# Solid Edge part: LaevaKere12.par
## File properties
Author: Egon 815
Template: Normal.par
Last saved by: egono
Revision: 95
Application: Solid Edge
Accuracy: 0,990
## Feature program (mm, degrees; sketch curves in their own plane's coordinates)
boolean "unnamed Boolean 1"
sketch for "unnamed Protrusion 1" #1 plane through (16818.4775, 0, 0) normal (1, 0, 0) x-axis (0, 1, 0)
  arc centre (22553.4282, -4878.3254) radius 21853.533 from (699.8952, -4878.3254) to (5128.0164, 8310) cw
  arc centre (-22553.4282, -4878.3254) radius 21853.533 from (-699.8952, -4878.3254) to (-5128.0164, 8310) ccw
  line (-5128.0164, 8310) -> (5128.0164, 8310)
  arc centre (0, -4878.3254) radius 699.8952 from (-699.8952, -4878.3254) to (0, -5578.2207) ccw
  arc centre (0, -4878.3254) radius 699.8952 from (0, -5578.2207) to (699.8952, -4878.3254) ccw
sketch for "unnamed Protrusion 1" #2 plane through (16818.4775, 0, 0) normal (1, 0, 0) x-axis (0, 1, 0)
sketch for "unnamed Protrusion 1" #3 plane through (16818.4775, 0, 0) normal (1, 0, 0) x-axis (0, 1, 0)
sketch for "unnamed Protrusion 1" #4 plane through (16818.4775, 0, 0) normal (1, 0, 0) x-axis (0, 1, 0)
sketch for "unnamed Protrusion 1" #5 plane through (16818.4775, 0, 0) normal (1, 0, 0) x-axis (0, 1, 0)
sketch for "unnamed Protrusion 1" #6 plane through (16818.4775, 0, 0) normal (1, 0, 0) x-axis (0, 1, 0)
sketch for "unnamed Protrusion 1" #7 plane through (16818.4775, 0, 0) normal (1, 0, 0) x-axis (0, 1, 0)
sketch for "unnamed Protrusion 1" #8 plane through (16818.4775, 0, 0) normal (1, 0, 0) x-axis (0, 1, 0)
sketch for "unnamed Protrusion 1" #9 plane through (16818.4775, 0, 0) normal (1, 0, 0) x-axis (0, 1, 0)
sketch for "unnamed Protrusion 1" #10 plane through (16818.4775, 0, 0) normal (1, 0, 0) x-axis (0, 1, 0)
sketch for "unnamed Protrusion 1" #11 plane through (16818.4775, 0, 0) normal (1, 0, 0) x-axis (0, 1, 0)
sketch for "unnamed Protrusion 1" #12 plane through (16818.4775, 0, 0) normal (1, 0, 0) x-axis (0, 1, 0)
sketch for "unnamed Protrusion 1" #13 plane through (16818.4775, 0, 0) normal (1, 0, 0) x-axis (0, 1, 0)
  line (-55694.7482, 3362.4841) -> (-45802.5294, 3362.4841)
  line (-45802.5294, 3362.4841) -> (-45802.5294, 843.2206)
  line (-45802.5294, 843.2206) -> (-55694.7482, 843.2206)
sketch for "unnamed Protrusion 1" #14 plane through (16818.4775, 0, 0) normal (1, 0, 0) x-axis (0, 1, 0)
extrude "unnamed Protrusion 1" add through along -normal
boolean "unnamed Boolean 2"
sketch used by "ExtrudedProtrusion_12" plane through (0, 0, 0) normal (1, 0, 0) x-axis (0, 1, 0)
extrude "ExtrudedProtrusion_12" add finite 37845.8186 along -normal
replace surface "unnamed ReplaceSurface 1"
replace surface "unnamed ReplaceSurface 2"
body pattern "unnamed BodyPattern 1"
pattern "unnamed Pattern 1"
lofted protrusion "LoftedProtrusion_35"  StartTangentMagnitude1 = 1; EndTangentMagnitude1 = 1
sketch used by "unnamed Cutout 1" plane through (0, 0, 0) normal (1, 0, 0) x-axis (0, 1, 0)
  line (-111469.4186, 8314.9532) -> (-66244.3403, 7184.8312)
  line (-44381.2454, 5032.5774) -> (-59033.8334, 5032.5774)
  line (-59033.8334, 5032.5774) -> (-66244.3403, 7184.8312)
  line (-44381.2454, 5032.5774) -> (120116.3176, 5032.5774)
extrude "unnamed Cutout 1" cut through
Other named dimensions: "ExtrudedSurface_10": FiniteDepth = 28411.8747 mm | "OffsetSurface_9": Distance = 60 mm
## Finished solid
Body 1: sheet body, 1 face, 4 edges, 4 vertices.
  Faces by surface: offset 1
  Edges by curve: curve on surface 4
Body 2: sheet body, 2 faces, 7 edges, 6 vertices.
  Faces by surface: spline 2
  Edges by curve: spline 5, curve on surface 1, intersection 1
Body 3: sheet body, 1 face, 4 edges, 4 vertices.
  Faces by surface: swept 1
  Edges by curve: line 2, spline 2
Body 4: sheet body, 5 faces, 16 edges, 12 vertices.
  Faces by surface: spline 5
  Edges by curve: circle 10, spline 6
Body 5: solid body, 140 faces, 359 edges, 235 vertices.
  Faces by surface: plane 52, spline 48, swept 30, offset 10
  Edges by curve: intersection 222, line 80, spline 38, curve on surface 16, circle 3
Body 6: sheet body, 5 faces, 16 edges, 12 vertices.
  Faces by surface: spline 5
  Edges by curve: circle 10, spline 6
Bounding box of the edges (mm; curved faces can reach further): 34146.599 x 223480.463 x 17722.997, from (-17059.482, -111592.4206, -9412.9967) to (17087.1168, 111888.0426, 8310).
Planar faces by outward normal: +y 13, +z 12, -y 9, -z 9, oblique 9
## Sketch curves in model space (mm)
line (0, -58110, -8419.563) -> (0, -100110, -6634.2763)
arc centre (0, -94180.934, 9804.7076) radius 17475.5262 from (0, -100110, -6634.2763) through (0, -108038.3579, -842.631) to (0, -111592.4206, 8310)
line (0, -111592.4206, 8310) -> (0, -58110, 8310)
line (0, -58110, 8310) -> (0, -58110, -8419.563)
line (0, 58110, 0) -> (0, 121328.7038, 0)
arc centre (0, -94180.934, 9804.7076) radius 17475.5262 from (0, -100110, -6634.2763) through (0, -108038.3579, -842.631) to (0, -111592.4206, 8310)
arc centre (0, -66819.8022, 281607.7742) radius 290158.0896 from (0, -58110, -8419.563) through (0, -79142.3739, -8288.5369) to (0, -100110, -6634.2763)
spline (0, 108319.1409, -466.861) -> (0, 87426.5717, -1716.8383) -> (0, 74368.3125, -7728.4737)
spline (0, 111888.0426, 5818.6126) -> (0, 79249.523, -627.6963) -> (0, 61996.5318, -8357.1547)
spline (0, -111592.4206, 8310) -> (6396.3752, -95897.2038, 8310) -> (11499.3187, -58110, 8310)
spline (16818.4775, -45803.1644, 2828.5884) -> (16818.4775, -45992.3683, 2095.2187) -> (16818.4775, -46181.5723, 1361.8491)
spline (16818.4775, -45938.388, 2828.5884) -> (16818.4775, -45870.7762, 2828.5884) -> (16818.4775, -45803.1644, 2828.5884)
spline (16818.4775, -46230.6453, 1708.6321) -> (16818.4775, -46084.5167, 2268.6102) -> (16818.4775, -45938.388, 2828.5884)
spline (16818.4775, -46533.8078, 2827.4979) -> (16818.4775, -46382.2266, 2268.065) -> (16818.4775, -46230.6453, 1708.6321)
spline (16818.4775, -46669.0314, 2828.5884) -> (16818.4775, -46601.4196, 2828.0432) -> (16818.4775, -46533.8078, 2827.4979)
spline (16818.4775, -46289.533, 1361.8491) -> (16818.4775, -46479.2822, 2095.2187) -> (16818.4775, -46669.0314, 2828.5884)
spline (16818.4775, -46181.5723, 1361.8491) -> (16818.4775, -46235.5526, 1361.8491) -> (16818.4775, -46289.533, 1361.8491)
spline (16818.4775, -47007.0903, 2186.2765) -> (16818.4775, -47007.0903, 2293.1468) -> (16818.4775, -47007.0903, 2400.017)
spline (16818.4775, -47556.7086, 2186.2765) -> (16818.4775, -47281.8994, 2186.2765) -> (16818.4775, -47007.0903, 2186.2765)
spline (16818.4775, -47455.2909, 2632.2962) -> (16818.4775, -47555.9512, 2427.6933) -> (16818.4775, -47556.7086, 2186.2765)
spline (16818.4775, -47007.0903, 2400.017) -> (16818.4775, -47148.5364, 2663.0967) -> (16818.4775, -47455.2909, 2632.2962)
spline (16818.4775, -46984.1895, 2719.5372) -> (16818.4775, -46864.2331, 2400.7801) -> (16818.4775, -46864.2331, 2048.872)
spline (16818.4775, -47279.7184, 2835.1315) -> (16818.4775, -47118.4589, 2805.5514) -> (16818.4775, -46984.1895, 2719.5372)
spline (16818.4775, -46887.1339, 1361.8491) -> (16818.4775, -47707.1993, 1878.4972) -> (16818.4775, -47279.7184, 2835.1315)
spline (16818.4775, -46887.1339, 1502.5252) -> (16818.4775, -46887.1339, 1432.1871) -> (16818.4775, -46887.1339, 1361.8491)
spline (16818.4775, -47556.7086, 2048.872) -> (16818.4775, -47456.6582, 1526.6601) -> (16818.4775, -46887.1339, 1502.5252)
spline (16818.4775, -46864.2331, 2048.872) -> (16818.4775, -47210.4708, 2048.872) -> (16818.4775, -47556.7086, 2048.872)
spline (16818.4775, -48250.2746, 2691.1839) -> (16818.4775, -48790.0783, 2027.5951) -> (16818.4775, -48250.2746, 1714.0846)
spline (16818.4775, -48250.2746, 1714.0846) -> (16818.4775, -48250.2746, 2202.6342) -> (16818.4775, -48250.2746, 2691.1839)
spline (16818.4775, -47943.8405, 1512.3398) -> (16818.4775, -47943.8405, 1440.366) -> (16818.4775, -47943.8405, 1368.3921)
spline (16818.4775, -48106.3269, 2828.5884) -> (16818.4775, -48106.3269, 2124.633) -> (16818.4775, -47943.8405, 1512.3398)
spline (16818.4775, -48195.7489, 1474.1719) -> (16818.4775, -48934.0259, 2114.4439) -> (16818.4775, -48106.3269, 2828.5884)
spline (16818.4775, -47943.8405, 1368.3921) -> (16818.4775, -48083.6504, 1377.6938) -> (16818.4775, -48195.7489, 1474.1719)
spline (16818.4775, -49154.3095, 1505.7967) -> (16818.4775, -49154.3095, 1433.8229) -> (16818.4775, -49154.3095, 1361.8491)
spline (16818.4775, -49717.0139, 1505.7967) -> (16818.4775, -49435.6617, 1505.7967) -> (16818.4775, -49154.3095, 1505.7967)
spline (16818.4775, -49717.0139, 3361.8491) -> (16818.4775, -49717.0139, 2433.8229) -> (16818.4775, -49717.0139, 1505.7967)
spline (16818.4775, -49860.9616, 3361.8491) -> (16818.4775, -49788.9878, 3361.8491) -> (16818.4775, -49717.0139, 3361.8491)
spline (16818.4775, -49860.9616, 1361.8491) -> (16818.4775, -49860.9616, 2361.8491) -> (16818.4775, -49860.9616, 3361.8491)
spline (16818.4775, -49154.3095, 1361.8491) -> (16818.4775, -49507.6355, 1361.8491) -> (16818.4775, -49860.9616, 1361.8491)
spline (16818.4775, -51029.991, 2819.8643) -> (16818.4775, -51029.991, 2092.4925) -> (16818.4775, -51029.991, 1365.1206)
spline (16818.4775, -51177.2102, 2819.8643) -> (16818.4775, -51103.6006, 2819.8643) -> (16818.4775, -51029.991, 2819.8643)
spline (16818.4775, -51177.2102, 1365.1206) -> (16818.4775, -51177.2102, 2092.4925) -> (16818.4775, -51177.2102, 2819.8643)
spline (16818.4775, -51029.991, 1365.1206) -> (16818.4775, -51103.6006, 1365.1206) -> (16818.4775, -51177.2102, 1365.1206)
spline (16818.4775, -51029.991, 3361.8491) -> (16818.4775, -51029.991, 3256.6146) -> (16818.4775, -51029.991, 3151.3801)
spline (16818.4775, -51177.2102, 3361.8491) -> (16818.4775, -51103.6006, 3361.8491) -> (16818.4775, -51029.991, 3361.8491)
spline (16818.4775, -51177.2102, 3151.3801) -> (16818.4775, -51177.2102, 3256.6146) -> (16818.4775, -51177.2102, 3361.8491)
spline (16818.4775, -51029.991, 3151.3801) -> (16818.4775, -51103.6006, 3151.3801) -> (16818.4775, -51177.2102, 3151.3801)
spline (16818.4775, -52321.1579, 2822.0454) -> (16818.4775, -51538.1699, 2419.0178) -> (16818.4775, -51538.1699, 1355.306)
spline (16818.4775, -52321.1579, 1358.5775) -> (16818.4775, -52321.1579, 2090.3114) -> (16818.4775, -52321.1579, 2822.0454)
spline (16818.4775, -52177.2102, 1355.306) -> (16818.4775, -52249.184, 1356.9418) -> (16818.4775, -52321.1579, 1358.5775)
spline (16818.4775, -52177.2102, 2668.2831) -> (16818.4775, -52177.2102, 2011.7945) -> (16818.4775, -52177.2102, 1355.306)
spline (16818.4775, -51727.919, 2615.9385) -> (16818.4775, -51945.6793, 2668.2831) -> (16818.4775, -52177.2102, 2668.2831)
spline (16818.4775, -51682.1175, 1355.306) -> (16818.4775, -51682.1175, 1990.0487) -> (16818.4775, -51727.919, 2615.9385)
spline (16818.4775, -51538.1699, 1355.306) -> (16818.4775, -51610.1437, 1355.306) -> (16818.4775, -51682.1175, 1355.306)
spline (16818.4775, -52838.0608, 1599.5808) -> (16818.4775, -52788.0336, 1696.0912) -> (16818.4775, -52771.5396, 1815.5023)
spline (16818.4775, -53221.9212, 1575.5895) -> (16818.4775, -53016.6878, 1500.0124) -> (16818.4775, -52838.0608, 1599.5808)
spline (16818.4775, -53224.1023, 2619.21) -> (16818.4775, -53323.3389, 2096.8499) -> (16818.4775, -53221.9212, 1575.5895)
spline (16818.4775, -52838.0608, 2590.8567) -> (16818.4775, -53018.3012, 2690.5523) -> (16818.4775, -53224.1023, 2619.21)
spline (16818.4775, -52771.5396, 1815.5023) -> (16818.4775, -52771.5396, 2210.1978) -> (16818.4775, -52838.0608, 2590.8567)
spline (16818.4775, -52744.2767, 2707.5415) -> (16818.4775, -52624.3204, 2261.7589) -> (16818.4775, -52624.3204, 1784.9679)
spline (16818.4775, -53040.8961, 2835.1315) -> (16818.4775, -52879.0914, 2802.4161) -> (16818.4775, -52744.2767, 2707.5415)
spline (16818.4775, -52744.2767, 1481.8054) -> (16818.4775, -53467.2866, 1930.5519) -> (16818.4775, -53040.8961, 2835.1315)
spline (16818.4775, -52624.3204, 1784.9679) -> (16818.4775, -52654.4458, 1619.8916) -> (16818.4775, -52744.2767, 1481.8054)
spline (16818.4775, -53906.7631, 2684.6408) -> (16818.4775, -54448.7478, 2095.9867) -> (16818.4775, -53906.7631, 1505.7967)
spline (16818.4775, -53906.7631, 1505.7967) -> (16818.4775, -53906.7631, 2095.2187) -> (16818.4775, -53906.7631, 2684.6408)
spline (16818.4775, -53761.7249, 2825.3169) -> (16818.4775, -53761.7249, 1973.6266) -> (16818.4775, -53761.7249, 1121.9363)
spline (16818.4775, -54592.6955, 1633.3867) -> (16818.4775, -54587.2097, 2602.9457) -> (16818.4775, -53761.7249, 2825.3169)
spline (16818.4775, -54557.7991, 1494.8916) -> (16818.4775, -54576.4741, 1549.4172) -> (16818.4775, -54592.6955, 1633.3867)
spline (16818.4775, -53899.1295, 1361.8491) -> (16818.4775, -54253.1815, 1361.8491) -> (16818.4775, -54557.7991, 1494.8916)
spline (16818.4775, -53995.0946, 995.4369) -> (16818.4775, -53899.975, 1154.0061) -> (16818.4775, -53899.1295, 1361.8491)
spline (16818.4775, -54037.6246, 987.8033) -> (16818.4775, -54016.3596, 991.6201) -> (16818.4775, -53995.0946, 995.4369)
spline (16818.4775, -54592.6955, 987.8033) -> (16818.4775, -54315.1601, 987.8033) -> (16818.4775, -54037.6246, 987.8033)
spline (16818.4775, -54592.6955, 843.8556) -> (16818.4775, -54592.6955, 915.8294) -> (16818.4775, -54592.6955, 987.8033)
spline (16818.4775, -53835.8798, 926.7346) -> (16818.4775, -54202.1055, 843.8556) -> (16818.4775, -54592.6955, 843.8556)
spline (16818.4775, -53761.7249, 1121.9363) -> (16818.4775, -53779.991, 1016.5655) -> (16818.4775, -53835.8798, 926.7346)
spline (16818.4775, -54851.147, 1495.9821) -> (16818.4775, -54851.147, 1428.9156) -> (16818.4775, -54851.147, 1361.8491)
spline (16818.4775, -55550.1655, 1495.9821) -> (16818.4775, -55200.6562, 1495.9821) -> (16818.4775, -54851.147, 1495.9821)
spline (16818.4775, -55550.1655, 2396.7455) -> (16818.4775, -55550.1655, 1946.3638) -> (16818.4775, -55550.1655, 1495.9821)
spline (16818.4775, -55116.1415, 2396.7455) -> (16818.4775, -55333.1535, 2396.7455) -> (16818.4775, -55550.1655, 2396.7455)
spline (16818.4775, -55116.1415, 2537.4216) -> (16818.4775, -55116.1415, 2467.0835) -> (16818.4775, -55116.1415, 2396.7455)
spline (16818.4775, -55550.1655, 2537.4216) -> (16818.4775, -55333.1535, 2537.4216) -> (16818.4775, -55116.1415, 2537.4216)
spline (16818.4775, -55550.1655, 3217.9014) -> (16818.4775, -55550.1655, 2877.6615) -> (16818.4775, -55550.1655, 2537.4216)
spline (16818.4775, -54851.147, 3217.9014) -> (16818.4775, -55200.6562, 3217.9014) -> (16818.4775, -55550.1655, 3217.9014)
spline (16818.4775, -54851.147, 3361.8491) -> (16818.4775, -54851.147, 3289.8752) -> (16818.4775, -54851.147, 3217.9014)
spline (16818.4775, -55694.1132, 3361.8491) -> (16818.4775, -55272.6301, 3361.8491) -> (16818.4775, -54851.147, 3361.8491)
spline (16818.4775, -55694.1132, 1361.8491) -> (16818.4775, -55694.1132, 2361.8491) -> (16818.4775, -55694.1132, 3361.8491)
spline (16818.4775, -54851.147, 1361.8491) -> (16818.4775, -55272.6301, 1361.8491) -> (16818.4775, -55694.1132, 1361.8491)
spline (1815.8522, -98942.7597, -627.6741) -> (2610.5873, -98942.7597, 3198.1174) -> (5698.9261, -98942.7597, 8310)
spline (0, -98942.7597, -6683.892) -> (1090.9047, -98942.7597, -4829.0549) -> (1815.8522, -98942.7597, -627.6741)
line (-5128.0164, 100110, 8310) -> (5128.0164, 100110, 8310)
arc centre (-22553.4282, 100110, -4878.3254) radius 21853.533 from (-699.8952, 100110, -4878.3254) through (-1836.4821, 100110, 2077.6106) to (-5128.0164, 100110, 8310)
arc centre (0, 100110, -4878.3254) radius 699.8952 from (-699.8952, 100110, -4878.3254) through (-480.2973, 100110, -5387.4108) to (0, 100110, -5578.2207)
arc centre (0, 100110, -4878.3254) radius 699.8952 from (0, 100110, -5578.2207) through (509.0853, 100110, -5358.6227) to (699.8952, 100110, -4878.3254)
arc centre (22553.4282, 100110, -4878.3254) radius 21853.533 from (699.8952, 100110, -4878.3254) through (1836.4821, 100110, 2077.6106) to (5128.0164, 100110, 8310)
line (-5128.0164, -100110, 8310) -> (5128.0164, -100110, 8310)
arc centre (-22553.4282, -100110, -4878.3254) radius 21853.533 from (-699.8952, -100110, -4878.3254) through (-1836.4821, -100110, 2077.6106) to (-5128.0164, -100110, 8310)
arc centre (0, -100110, -4878.3254) radius 699.8952 from (-699.8952, -100110, -4878.3254) through (-480.2973, -100110, -5387.4108) to (0, -100110, -5578.2207)
arc centre (0, -100110, -4878.3254) radius 699.8952 from (699.8952, -100110, -4878.3254) through (480.2973, -100110, -5387.4108) to (0, -100110, -5578.2207)
arc centre (22553.4282, -100110, -4878.3254) radius 21853.533 from (699.8952, -100110, -4878.3254) through (1836.4821, -100110, 2077.6106) to (5128.0164, -100110, 8310)
line (0, -44381.2454, 5032.5774) -> (0, 120116.3176, 5032.5774)
line (0, -44381.2454, 5032.5774) -> (0, -59033.8334, 5032.5774)
line (0, -59033.8334, 5032.5774) -> (0, -66244.3403, 7184.8312)
line (0, -111469.4186, 8314.9532) -> (0, -66244.3403, 7184.8312)
line (0, -5463.7623, 7184.8312) -> (0, -5463.7623, 10563.589)
line (0, -42546.9286, 10563.589) -> (0, -5463.7623, 10563.589)
line (0, -42546.9286, 10563.589) -> (0, -53131.8324, 10563.589)
line (0, -53131.8324, 7184.8312) -> (0, -53131.8324, 10563.589)
arc centre (4185.1243, -58110, -12615.4047) radius 5926.2428 from (4371.7702, -58110, -6692.1018) through (2007.2841, -58110, -7103.8382) to (0, -58110, -8419.563)
arc centre (6098.5646, -58110, -470.8784) radius 6456.4262 from (9744.6378, -58110, -5799.2543) through (7156.9605, -58110, -6839.9629) to (4371.7702, -58110, -6692.1018)
arc centre (1803.2627, -58110, -494.6187) radius 9550.1099 from (11353.3694, -58110, -486.8867) through (10943.4649, -58110, -3262.5242) to (9744.6378, -58110, -5799.2543)
arc centre (72636.1358, -58110, 2896.0245) radius 61376.0665 from (11353.3694, -58110, -486.8867) through (11268.5148, -58110, 3914.1752) to (11499.3187, -58110, 8310)
line (-19950.5693, 0, 45450.8749) -> (-19950.5693, 0, -11537.5418)
line (19465.6098, 0, 45450.8749) -> (-19950.5693, 0, 45450.8749)
line (19465.6098, 0, -11537.5418) -> (19465.6098, 0, 45450.8749)
line (-19950.5693, 0, -11537.5418) -> (19465.6098, 0, -11537.5418)
line (0, 0, 44802.9635) -> (0, 0, -9317.0365)
line (17000, 0, 0) -> (-17000, 0, 0)
line (0, -121743.1574, 63248.4949) -> (0, -121743.1574, -26111.4194)
line (0, 114388.0141, 63248.4949) -> (0, -121743.1574, 63248.4949)
line (0, 114388.0141, -26111.4194) -> (0, 114388.0141, 63248.4949)
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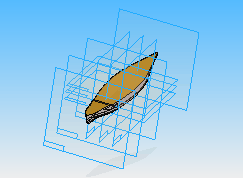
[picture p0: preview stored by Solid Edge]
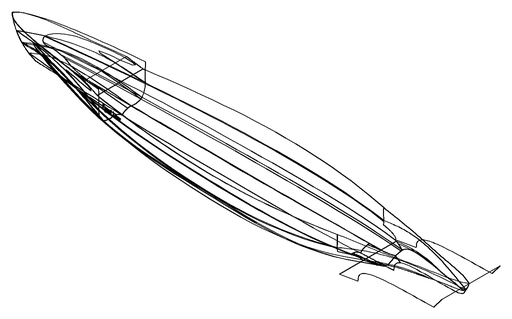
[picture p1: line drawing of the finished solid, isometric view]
